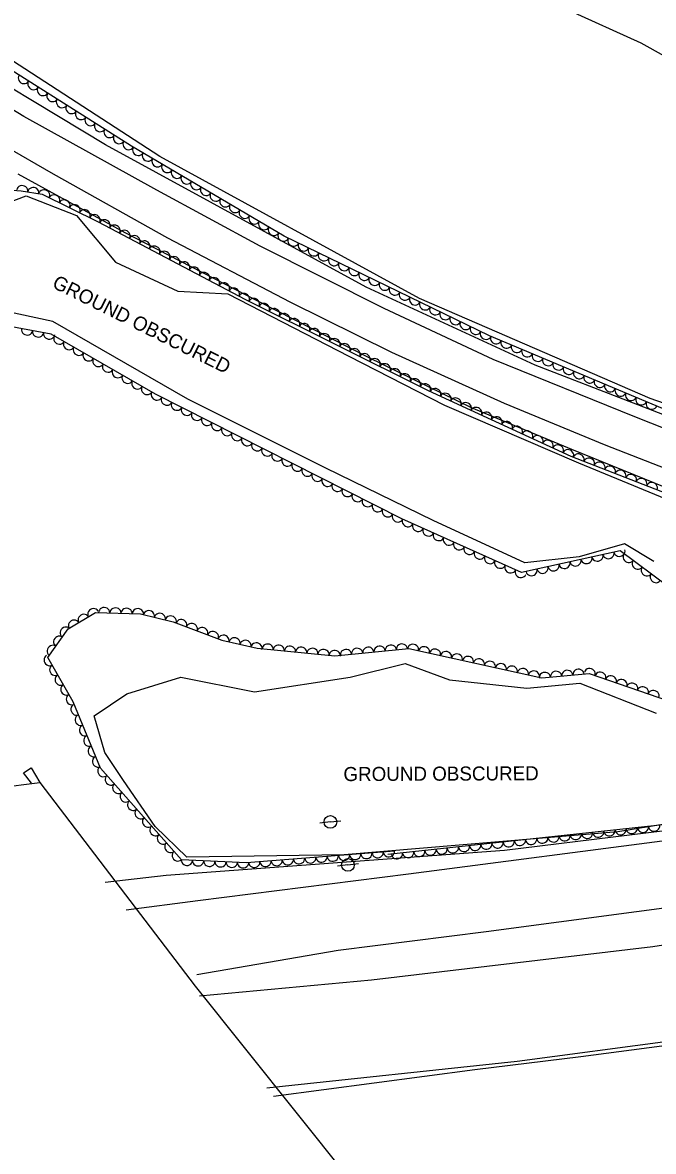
# Model space of a CAD drawing. Extents: x 1746719 to 1766531, y 631721 to 662391.
# Drawn here: x 1764923.1 to 1765147.4, y 632583.4 to 632984.7 of the extents above; entities that cross this region are included whole.
import ezdxf

# ---------------------------------------------------------------- set-up
doc = ezdxf.new("R2010")
doc.units = 0
for name, color, linetype in [('SURVEY - AERIAL SURVEY - Photo Control - Points - Elevations', 7, 'Continuous'), ('SURVEY - AERIAL SURVEY - Photo Control - Points - Locators', 7, 'Continuous'), ('SURVEY - AERIAL SURVEY - Photo Control with Text', 7, 'Continuous'), ('SURVEY - CENTERLINE - Existing Roads - Development', 7, 'Continuous'), ('SURVEY - CENTERLINE - Existing Roads Text', 7, 'Continuous')]:
    doc.layers.add(name, color=color, linetype=linetype)

msp = doc.modelspace()

# ---------------------------------------------------------------- linework, layer by layer
at = {"layer": 'SURVEY - AERIAL SURVEY - Photo Control - Points - Elevations'}
for points in [[(1765405.55, 632796.71), (1765330.18, 632801.39), (1765276.68, 632810.4), (1765227.62, 632820.45), (1765175.33, 632835.88), (1765105.4, 632862.94), (1765045.31, 632890.6), (1764952.52, 632941.27), (1764893.1, 632976.98), (1764852.73, 633007.31), (1764794.71, 633051.44), (1764731.05, 633102.95), (1764684.95, 633147.06), (1764630.12, 633206.72), (1764589.37, 633257.76), (1764542.78, 633315.43), (1764515.94, 633356.98), (1764503.08, 633378.08)], [(1765402.26, 632787.96), (1765361.2, 632790.5), (1765329.28, 632793.31), (1765292.46, 632799.51), (1765251.85, 632808.39), (1765215.1, 632818.14), (1765178.89, 632829.55), (1765140.77, 632844.55), (1765090.46, 632864.92), (1765051.71, 632883.1), (1765007.59, 632905.27), (1764970.77, 632925.15), (1764923.54, 632951.31), (1764880.2, 632977.66)], [(1765391.82, 632775.7), (1765360.92, 632777.57), (1765341.11, 632779.4), (1765324.33, 632781.23), (1765299.09, 632785.14), (1765276.61, 632789.6), (1765253.82, 632794.81), (1765231.23, 632800.66), (1765205.66, 632807.76), (1765181.65, 632815.3), (1765157.05, 632824.01), (1765130.08, 632834.58), (1765094.5, 632849.32), (1765054.39, 632867.46), (1765018.25, 632885.35), (1764974.76, 632908.1), (1764934.05, 632930.78), (1764898.68, 632951.21)], [(1764952.48, 632679.13), (1764974.15, 632681.64), (1765094.48, 632690.51), (1765183.35, 632701.44), (1765281.66, 632726.68), (1765343.44, 632739.05), (1765372.09, 632748.82), (1765371.55, 632753.36), (1765368.65, 632757.53), (1765339.3, 632772.92), (1765297.11, 632779.38), (1765261.51, 632786.73), (1765218.53, 632797.59), (1765190.3, 632804.88), (1765162.76, 632814.94), (1765118.36, 632832.93), (1765082.73, 632847.76), (1765046.16, 632865.6), (1765006.8, 632885.71), (1764959.62, 632910.01), (1764921.46, 632930.83)], [(1764959.86, 632669.29), (1764985.37, 632672.58), (1765060.29, 632682.11), (1765156.9, 632694.65), (1765232.5, 632706.41), (1765288.72, 632716.85), (1765340.55, 632728.51), (1765388.58, 632740.56), (1765439.4, 632754.72)], [(1764985, 632646.34), (1765035.31, 632655.01), (1765087.95, 632661.65), (1765167.23, 632672.1), (1765251.78, 632685.46), (1765339.51, 632703.93), (1765367.1, 632710.21), (1765376.53, 632708.95), (1765377.35, 632708.11), (1765378.23, 632706.75), (1765378.64, 632705.15), (1765377.49, 632703.57), (1765371.62, 632698.98), (1765367.73, 632697.3), (1765362.18, 632696.02), (1765331.43, 632688.57), (1765253.62, 632672.78), (1765147.19, 632656.13), (1765047.13, 632644.27), (1764986, 632638.62)], [(1765344.02, 632569.03), (1765327.17, 632583.68), (1765304.27, 632599.56), (1765285.42, 632609.4), (1765261.41, 632618.77), (1765241.44, 632624.18), (1765220.16, 632626.94), (1765194.12, 632626.8), (1765154.28, 632622.77), (1765098.99, 632615.44), (1765009.92, 632605.91)], [(1765320.19, 632582.94), (1765297.73, 632597.9), (1765272.18, 632610.43), (1765243.85, 632618.9), (1765223.43, 632624.7), (1765190.37, 632624.79), (1765163.91, 632622.68), (1765121.59, 632617.07), (1765083.89, 632612.38), (1765012.26, 632602.97)]]:
    msp.add_lwpolyline(points, dxfattribs=at)
at = {"layer": 'SURVEY - AERIAL SURVEY - Photo Control - Points - Locators'}
for points in [[(1765420.59, 632799.81), (1765352.54, 632801.36), (1765306.68, 632807.82), (1765224.24, 632823.91), (1765146.28, 632851.08), (1765064.26, 632886.58), (1764971.89, 632937.15), (1764891.98, 632988.83), (1764834.38, 633027.43), (1764768.22, 633076.12), (1764713.93, 633122.52), (1764646.51, 633193.22), (1764650.11, 633212.47), (1764635.34, 633243.35), (1764619.24, 633269.36), (1764613.9, 633275.29)], [(1764909.25, 633068.37), (1764938.84, 633053.98), (1764965.49, 633051.38), (1764990.14, 633044.09), (1765000.39, 633032.01), (1765031.93, 633011.83), (1765053.24, 632994.52), (1765083.38, 632993.91), (1765116.7, 632989.36), (1765142.91, 632977.46), (1765166.84, 632964.22), (1765179.57, 632940.86), (1765182.57, 632929.75), (1765206.98, 632913.55), (1765238.34, 632894.81), (1765265.57, 632881.71), (1765294.15, 632875.06), (1765330.01, 632866.88), (1765360.91, 632861.63), (1765392.72, 632858.38)], [(1764916.54, 632920.19), (1764924.4, 632923.1), (1764942.26, 632916.18), (1764956.15, 632899.5), (1764978.28, 632889.26), (1764996.07, 632888.31), (1765039.09, 632866.16), (1765073.09, 632848.69)], [(1765147.54, 632793.13), (1765137.16, 632799.42), (1765121.03, 632794.74), (1765101.74, 632792.61), (1765069.14, 632807.75), (1765030.92, 632826.31), (1764981.81, 632850.84), (1764933.87, 632878.5), (1764905.14, 632884.63)], [(1765073.09, 632848.69), (1765120.74, 632828.22), (1765172.79, 632806.71)], [(1765199.4, 632707.59), (1765134.82, 632697.01), (1765037.41, 632688.82), (1764981.47, 632688.01), (1764970.18, 632698.99), (1764959, 632715.24), (1764952.37, 632725.25), (1764948.57, 632738.24), (1764960.12, 632746.13), (1764979.32, 632751.99), (1765005.59, 632746.85), (1765039.53, 632752.06), (1765059.2, 632756.84), (1765074.9, 632751.06), (1765102.46, 632748.09), (1765121.25, 632749.92), (1765148.44, 632739.25)]]:
    msp.add_lwpolyline(points, dxfattribs=at)
at = {"layer": 'SURVEY - AERIAL SURVEY - Photo Control with Text'}
for points in [[(1765421.97, 632798.07), (1765349.97, 632800.91), (1765276.72, 632812.18), (1765214.84, 632825.79), (1765152.86, 632846.61), (1765089.11, 632873.35), (1765016.1, 632908.74), (1764961.81, 632940.76), (1764903.95, 632977.24), (1764850.97, 633012.42), (1764802.27, 633048.67), (1764748.05, 633090.52), (1764703.67, 633131.64), (1764646.25, 633191), (1764640.08, 633203.27), (1764641.2, 633222.14), (1764617.56, 633262.33), (1764604.44, 633282.31), (1764595.81, 633316.48), (1764603.61, 633330.78)], [(1764793.84, 632968), (1764782.2, 632980.66), (1764777.93, 632995.28), (1764790.08, 633001.97), (1764812.82, 632992.23), (1764867.11, 632954.7), (1764908.11, 632925.96), (1764922.59, 632924.95), (1764930.06, 632923.7), (1764950.01, 632913.91), (1765002.14, 632886.38), (1765067.3, 632853.88), (1765118.03, 632830.56), (1765171.36, 632809.82), (1765229.12, 632790.58), (1765287.61, 632773.65), (1765303.5, 632750.65), (1765303.15, 632741.87), (1765286.32, 632729.03), (1765268.97, 632724.98), (1765183.81, 632703.05), (1765052.93, 632688.94)], [(1765152.84, 632784.11), (1765135.58, 632796.9), (1765100.57, 632789.17), (1765058, 632808.29), (1764970.3, 632852.64), (1764933.26, 632873.94), (1764901.9, 632879.73)], [(1765055.33, 632690.16), (1765002.73, 632686.03), (1764979.58, 632687.05), (1764950.77, 632719.66), (1764941.02, 632743.26), (1764932.05, 632759.05), (1764939.27, 632769.18), (1764949.06, 632774.99), (1764964.97, 632774.49), (1764976.67, 632771.7), (1764993.95, 632765.2), (1765006.54, 632762.28), (1765034.16, 632759.65), (1765060.39, 632762.17), (1765107.72, 632751.76), (1765124.53, 632753.3), (1765166.96, 632738.76)]]:
    msp.add_lwpolyline(points, dxfattribs=at)
for centre, major_axis in [((1764923.51, 632964.91), (-1.69, 1.07)), ((1764926.89, 632962.77), (-1.69, 1.07)), ((1764930.27, 632960.64), (-1.69, 1.07)), ((1764933.66, 632958.51), (-1.69, 1.07)), ((1764937.04, 632956.37), (-1.69, 1.07)), ((1764940.42, 632954.24), (-1.69, 1.07)), ((1764943.81, 632952.11), (-1.69, 1.07)), ((1764947.19, 632949.97), (-1.69, 1.07)), ((1764950.57, 632947.84), (-1.69, 1.07)), ((1764953.96, 632945.71), (-1.69, 1.07)), ((1764957.34, 632943.57), (-1.69, 1.07)), ((1764960.72, 632941.44), (-1.69, 1.07)), ((1764964.15, 632939.37), (-1.72, 1.02)), ((1764967.6, 632937.34), (-1.72, 1.02)), ((1764971.04, 632935.31), (-1.72, 1.02)), ((1764974.49, 632933.28), (-1.72, 1.02)), ((1764977.93, 632931.25), (-1.72, 1.02)), ((1764922.96, 632924.88), (1.97, -0.33)), ((1764981.38, 632929.22), (-1.72, 1.02)), ((1764984.82, 632927.18), (-1.72, 1.02)), ((1764926.91, 632924.23), (1.97, -0.33)), ((1764930.78, 632923.35), (1.8, -0.88)), ((1764934.37, 632921.59), (1.8, -0.88)), ((1764988.27, 632925.15), (-1.72, 1.02)), ((1764991.72, 632923.12), (-1.72, 1.02)), ((1764937.97, 632919.82), (1.8, -0.88)), ((1764941.56, 632918.06), (1.8, -0.88)), ((1764945.15, 632916.3), (1.8, -0.88)), ((1764995.16, 632921.09), (-1.72, 1.02)), ((1764998.61, 632919.06), (-1.72, 1.02)), ((1764948.74, 632914.54), (1.8, -0.88)), ((1764952.29, 632912.71), (1.77, -0.93)), ((1765002.05, 632917.03), (-1.72, 1.02)), ((1765005.5, 632915), (-1.72, 1.02)), ((1764955.83, 632910.84), (1.77, -0.93)), ((1764959.37, 632908.97), (1.77, -0.93)), ((1765008.94, 632912.96), (-1.72, 1.02)), ((1765012.39, 632910.93), (-1.72, 1.02)), ((1764962.91, 632907.1), (1.77, -0.93)), ((1764966.44, 632905.23), (1.77, -0.93)), ((1765015.84, 632908.9), (-1.72, 1.02)), ((1765019.42, 632907.13), (-1.8, 0.87)), ((1764969.98, 632903.37), (1.77, -0.93)), ((1764973.52, 632901.5), (1.77, -0.93)), ((1765023.02, 632905.39), (-1.8, 0.87)), ((1765026.62, 632903.64), (-1.8, 0.87)), ((1765030.22, 632901.9), (-1.8, 0.87)), ((1764977.05, 632899.63), (1.77, -0.93)), ((1764980.59, 632897.76), (1.77, -0.93)), ((1765033.82, 632900.15), (-1.8, 0.87)), ((1765037.42, 632898.41), (-1.8, 0.87)), ((1764984.13, 632895.89), (1.77, -0.93)), ((1764987.66, 632894.02), (1.77, -0.93)), ((1764991.2, 632892.16), (1.77, -0.93)), ((1765041.02, 632896.66), (-1.8, 0.87)), ((1765044.62, 632894.92), (-1.8, 0.87)), ((1764994.74, 632890.29), (1.77, -0.93)), ((1764998.27, 632888.42), (1.77, -0.93)), ((1765048.22, 632893.17), (-1.8, 0.87)), ((1765051.82, 632891.43), (-1.8, 0.87)), ((1765055.42, 632889.68), (-1.8, 0.87)), ((1765001.81, 632886.55), (1.77, -0.93)), ((1765005.39, 632884.76), (1.79, -0.89)), ((1765059.01, 632887.94), (-1.8, 0.87)), ((1765062.61, 632886.19), (-1.8, 0.87)), ((1765008.97, 632882.97), (1.79, -0.89)), ((1765012.55, 632881.19), (1.79, -0.89)), ((1765066.21, 632884.45), (-1.8, 0.87)), ((1765069.81, 632882.7), (-1.8, 0.87)), ((1765016.13, 632879.4), (1.79, -0.89)), ((1765019.7, 632877.62), (1.79, -0.89)), ((1765073.41, 632880.96), (-1.8, 0.87)), ((1765077.01, 632879.21), (-1.8, 0.87)), ((1765080.61, 632877.47), (-1.8, 0.87)), ((1764924.69, 632875.52), (-1.97, 0.36)), ((1764928.62, 632874.8), (-1.97, 0.36)), ((1764932.56, 632874.07), (-1.97, 0.36)), ((1765023.28, 632875.83), (1.79, -0.89)), ((1765026.86, 632874.05), (1.79, -0.89)), ((1765030.44, 632872.26), (1.79, -0.89)), ((1765084.21, 632875.72), (-1.8, 0.87)), ((1765087.81, 632873.98), (-1.8, 0.87)), ((1764936.11, 632872.3), (-1.73, 1)), ((1764939.57, 632870.31), (-1.73, 1)), ((1765034.02, 632870.48), (1.79, -0.89)), ((1765037.6, 632868.69), (1.79, -0.89)), ((1765091.46, 632872.36), (-1.84, 0.77)), ((1765095.15, 632870.81), (-1.84, 0.77)), ((1764943.04, 632868.31), (-1.73, 1)), ((1764946.51, 632866.32), (-1.73, 1)), ((1765041.18, 632866.91), (1.79, -0.89)), ((1765044.76, 632865.12), (1.79, -0.89)), ((1765098.84, 632869.26), (-1.84, 0.77)), ((1765102.53, 632867.72), (-1.84, 0.77)), ((1765106.22, 632866.17), (-1.84, 0.77)), ((1764949.98, 632864.33), (-1.73, 1)), ((1764953.44, 632862.33), (-1.73, 1)), ((1765048.34, 632863.34), (1.79, -0.89)), ((1765051.92, 632861.55), (1.79, -0.89)), ((1765109.91, 632864.62), (-1.84, 0.77)), ((1765113.6, 632863.08), (-1.84, 0.77)), ((1765117.29, 632861.53), (-1.84, 0.77)), ((1764956.91, 632860.34), (-1.73, 1)), ((1764960.38, 632858.34), (-1.73, 1)), ((1765055.5, 632859.77), (1.79, -0.89)), ((1765059.08, 632857.98), (1.79, -0.89)), ((1765062.66, 632856.2), (1.79, -0.89)), ((1765120.97, 632859.98), (-1.84, 0.77)), ((1765124.66, 632858.44), (-1.84, 0.77)), ((1764963.85, 632856.35), (-1.73, 1)), ((1764967.31, 632854.36), (-1.73, 1)), ((1765066.24, 632854.41), (1.79, -0.89)), ((1765069.86, 632852.71), (1.82, -0.84)), ((1765128.35, 632856.89), (-1.84, 0.77)), ((1765132.04, 632855.34), (-1.84, 0.77)), ((1765135.73, 632853.79), (-1.84, 0.77)), ((1764970.8, 632852.39), (-1.78, 0.9)), ((1764974.36, 632850.58), (-1.78, 0.9)), ((1765073.49, 632851.04), (1.82, -0.84)), ((1765077.13, 632849.37), (1.82, -0.84)), ((1765139.42, 632852.25), (-1.84, 0.77)), ((1765143.11, 632850.7), (-1.84, 0.77)), ((1764977.93, 632848.78), (-1.78, 0.9)), ((1764981.5, 632846.97), (-1.78, 0.9)), ((1765080.76, 632847.7), (1.82, -0.84)), ((1765084.4, 632846.03), (1.82, -0.84)), ((1765088.03, 632844.35), (1.82, -0.84)), ((1765146.8, 632849.15), (-1.84, 0.77)), ((1764985.07, 632845.17), (-1.78, 0.9)), ((1764988.64, 632843.36), (-1.78, 0.9)), ((1764992.21, 632841.56), (-1.78, 0.9)), ((1765091.66, 632842.68), (1.82, -0.84)), ((1765095.3, 632841.01), (1.82, -0.84)), ((1764995.78, 632839.75), (-1.78, 0.9)), ((1764999.35, 632837.95), (-1.78, 0.9)), ((1765098.93, 632839.34), (1.82, -0.84)), ((1765102.57, 632837.67), (1.82, -0.84)), ((1765106.2, 632836), (1.82, -0.84)), ((1765002.92, 632836.14), (-1.78, 0.9)), ((1765006.49, 632834.34), (-1.78, 0.9)), ((1765109.84, 632834.33), (1.82, -0.84)), ((1765113.47, 632832.66), (1.82, -0.84)), ((1765010.06, 632832.53), (-1.78, 0.9)), ((1765013.63, 632830.73), (-1.78, 0.9)), ((1765117.1, 632830.99), (1.82, -0.84)), ((1765120.81, 632829.48), (1.86, -0.73)), ((1765124.54, 632828.03), (1.86, -0.73)), ((1765017.2, 632828.92), (-1.78, 0.9)), ((1765020.77, 632827.12), (-1.78, 0.9)), ((1765024.34, 632825.31), (-1.78, 0.9)), ((1765128.26, 632826.58), (1.86, -0.73)), ((1765131.99, 632825.13), (1.86, -0.73)), ((1765027.91, 632823.51), (-1.78, 0.9)), ((1765031.48, 632821.7), (-1.78, 0.9)), ((1765135.72, 632823.68), (1.86, -0.73)), ((1765139.45, 632822.23), (1.86, -0.73)), ((1765143.18, 632820.78), (1.86, -0.73)), ((1765035.05, 632819.9), (-1.78, 0.9)), ((1765038.62, 632818.09), (-1.78, 0.9)), ((1765146.9, 632819.33), (1.86, -0.73)), ((1765042.19, 632816.29), (-1.78, 0.9)), ((1765045.76, 632814.48), (-1.78, 0.9)), ((1765049.33, 632812.68), (-1.78, 0.9)), ((1765052.9, 632810.87), (-1.78, 0.9)), ((1765056.47, 632809.07), (-1.78, 0.9)), ((1765060.08, 632807.36), (-1.82, 0.82)), ((1765063.73, 632805.72), (-1.82, 0.82)), ((1765067.38, 632804.08), (-1.82, 0.82)), ((1765071.03, 632802.44), (-1.82, 0.82)), ((1765074.67, 632800.8), (-1.82, 0.82)), ((1765078.32, 632799.16), (-1.82, 0.82)), ((1765081.97, 632797.52), (-1.82, 0.82)), ((1765085.62, 632795.88), (-1.82, 0.82)), ((1765089.27, 632794.24), (-1.82, 0.82)), ((1765123.62, 632794.26), (-1.95, -0.43)), ((1765127.53, 632795.12), (-1.95, -0.43)), ((1765131.44, 632795.99), (-1.95, -0.43)), ((1765135.34, 632796.85), (-1.95, -0.43)), ((1765138.6, 632794.67), (-1.61, 1.19)), ((1765092.92, 632792.6), (-1.82, 0.82)), ((1765096.57, 632790.96), (-1.82, 0.82)), ((1765100.22, 632789.33), (-1.82, 0.82)), ((1765104.1, 632789.94), (-1.95, -0.43)), ((1765108, 632790.81), (-1.95, -0.43)), ((1765111.91, 632791.67), (-1.95, -0.43)), ((1765115.81, 632792.53), (-1.95, -0.43)), ((1765119.72, 632793.4), (-1.95, -0.43)), ((1765141.81, 632792.29), (-1.61, 1.19)), ((1765145.03, 632789.9), (-1.61, 1.19)), ((1765148.24, 632787.52), (-1.61, 1.19)), ((1764944.79, 632772.46), (1.72, 1.02)), ((1764948.23, 632774.5), (1.72, 1.02)), ((1764952.09, 632774.9), (2, -0.06)), ((1764956.09, 632774.77), (2, -0.06)), ((1764960.08, 632774.65), (2, -0.06)), ((1764964.08, 632774.52), (2, -0.06)), ((1764968, 632773.77), (1.95, -0.46)), ((1764971.89, 632772.84), (1.95, -0.46)), ((1764975.78, 632771.91), (1.95, -0.46)), ((1764938.35, 632767.89), (1.16, 1.63)), ((1764941.35, 632770.41), (1.72, 1.02)), ((1764979.56, 632770.61), (1.87, -0.7)), ((1764983.3, 632769.21), (1.87, -0.7)), ((1764987.04, 632767.8), (1.87, -0.7)), ((1764936.03, 632764.63), (1.16, 1.63)), ((1764990.79, 632766.39), (1.87, -0.7)), ((1764994.55, 632765.06), (1.95, -0.45)), ((1764998.45, 632764.16), (1.95, -0.45)), ((1764933.71, 632761.38), (1.16, 1.63)), ((1765002.35, 632763.25), (1.95, -0.45)), ((1765006.24, 632762.35), (1.95, -0.45)), ((1765010.22, 632761.93), (1.99, -0.19)), ((1765014.2, 632761.55), (1.99, -0.19)), ((1765018.18, 632761.17), (1.99, -0.19)), ((1765022.17, 632760.79), (1.99, -0.19)), ((1765026.15, 632760.41), (1.99, -0.19)), ((1765030.13, 632760.03), (1.99, -0.19)), ((1765038.09, 632760.03), (1.99, 0.19)), ((1765042.08, 632760.41), (1.99, 0.19)), ((1765046.06, 632760.79), (1.99, 0.19)), ((1765050.04, 632761.18), (1.99, 0.19)), ((1765054.02, 632761.56), (1.99, 0.19)), ((1765058, 632761.94), (1.99, 0.19)), ((1765061.95, 632761.83), (1.95, -0.43)), ((1765065.86, 632760.97), (1.95, -0.43)), ((1765069.77, 632760.11), (1.95, -0.43)), ((1764932.61, 632758.06), (-0.99, 1.74)), ((1765034.11, 632759.65), (1.99, -0.19)), ((1765073.67, 632759.25), (1.95, -0.43)), ((1765077.58, 632758.39), (1.95, -0.43)), ((1765081.49, 632757.53), (1.95, -0.43)), ((1765085.39, 632756.67), (1.95, -0.43)), ((1764934.59, 632754.58), (-0.99, 1.74)), ((1765089.3, 632755.81), (1.95, -0.43)), ((1765093.21, 632754.95), (1.95, -0.43)), ((1765097.11, 632754.09), (1.95, -0.43)), ((1765101.02, 632753.23), (1.95, -0.43)), ((1765104.92, 632752.37), (1.95, -0.43)), ((1765112.84, 632752.23), (1.99, 0.18)), ((1765116.82, 632752.59), (1.99, 0.18)), ((1765120.8, 632752.96), (1.99, 0.18)), ((1765124.77, 632753.22), (1.89, -0.65)), ((1765128.56, 632751.92), (1.89, -0.65)), ((1764936.56, 632751.1), (-0.99, 1.74)), ((1765108.85, 632751.86), (1.99, 0.18)), ((1765132.34, 632750.62), (1.89, -0.65)), ((1765136.12, 632749.32), (1.89, -0.65)), ((1765139.91, 632748.03), (1.89, -0.65)), ((1764938.54, 632747.62), (-0.99, 1.74)), ((1764940.51, 632744.14), (-0.99, 1.74)), ((1765143.69, 632746.73), (1.89, -0.65)), ((1765147.48, 632745.43), (1.89, -0.65)), ((1764942.16, 632740.5), (-0.76, 1.85)), ((1764943.68, 632736.8), (-0.76, 1.85)), ((1764945.21, 632733.11), (-0.76, 1.85)), ((1764946.74, 632729.41), (-0.76, 1.85)), ((1764948.27, 632725.71), (-0.76, 1.85)), ((1764949.79, 632722.02), (-0.76, 1.85)), ((1764951.73, 632718.57), (-1.32, 1.5)), ((1764954.38, 632715.58), (-1.32, 1.5)), ((1764957.02, 632712.58), (-1.32, 1.5)), ((1764959.67, 632709.58), (-1.32, 1.5)), ((1764962.32, 632706.58), (-1.32, 1.5)), ((1764964.97, 632703.58), (-1.32, 1.5)), ((1764967.62, 632700.59), (-1.32, 1.5)), ((1764970.27, 632697.59), (-1.32, 1.5)), ((1765135.76, 632697.87), (-1.99, -0.21)), ((1765139.74, 632698.29), (-1.99, -0.21)), ((1765143.71, 632698.72), (-1.99, -0.21)), ((1765147.69, 632699.15), (-1.99, -0.21)), ((1764972.91, 632694.59), (-1.32, 1.5)), ((1765095.99, 632693.58), (-1.99, -0.21)), ((1765099.97, 632694.01), (-1.99, -0.21)), ((1765103.94, 632694.43), (-1.99, -0.21)), ((1765107.92, 632694.86), (-1.99, -0.21)), ((1765111.9, 632695.29), (-1.99, -0.21)), ((1765115.88, 632695.72), (-1.99, -0.21)), ((1765119.85, 632696.15), (-1.99, -0.21)), ((1765123.83, 632696.58), (-1.99, -0.21)), ((1765127.81, 632697.01), (-1.99, -0.21)), ((1765131.78, 632697.44), (-1.99, -0.21)), ((1764975.56, 632691.59), (-1.32, 1.5)), ((1764978.21, 632688.6), (-1.32, 1.5)), ((1765049.35, 632689.69), (-1.99, -0.16)), ((1765053.33, 632690), (-1.99, -0.16)), ((1765060.2, 632689.72), (-1.99, -0.21)), ((1765064.18, 632690.15), (-1.99, -0.21)), ((1765068.15, 632690.58), (-1.99, -0.21)), ((1765072.13, 632691), (-1.99, -0.21)), ((1765076.11, 632691.43), (-1.99, -0.21)), ((1765080.08, 632691.86), (-1.99, -0.21)), ((1765084.06, 632692.29), (-1.99, -0.21)), ((1765088.04, 632692.72), (-1.99, -0.21)), ((1765092.01, 632693.15), (-1.99, -0.21)), ((1764981.51, 632686.96), (-2, 0.09)), ((1764985.51, 632686.79), (-2, 0.09)), ((1764989.5, 632686.61), (-2, 0.09)), ((1764993.5, 632686.43), (-2, 0.09)), ((1764997.49, 632686.26), (-2, 0.09)), ((1765001.49, 632686.08), (-2, 0.09)), ((1765005.48, 632686.24), (-1.99, -0.16)), ((1765009.47, 632686.56), (-1.99, -0.16)), ((1765013.46, 632686.87), (-1.99, -0.16)), ((1765017.44, 632687.18), (-1.99, -0.16)), ((1765021.43, 632687.5), (-1.99, -0.16)), ((1765025.42, 632687.81), (-1.99, -0.16)), ((1765029.41, 632688.12), (-1.99, -0.16)), ((1765033.39, 632688.44), (-1.99, -0.16)), ((1765037.38, 632688.75), (-1.99, -0.16)), ((1765041.37, 632689.06), (-1.99, -0.16)), ((1765045.36, 632689.38), (-1.99, -0.16)), ((1765056.22, 632689.29), (-1.99, -0.21))]:
    msp.add_ellipse(centre, major_axis=major_axis, ratio=0.940188, start_param=0, end_param=3.141593, dxfattribs=at)
at = {"layer": 'SURVEY - CENTERLINE - Existing Roads - Development'}
for p, q in [((1765032.57, 632700.57), (1765028.85, 632700.15)), ((1765032.57, 632700.57), (1765036.3, 632700.98)), ((1765038.78, 632685.28), (1765042.51, 632685.73)), ((1765038.78, 632685.28), (1765035.06, 632684.84))]:
    msp.add_line(p, q, dxfattribs=at)
for centre in [(1765032.57, 632700.57), (1765038.78, 632685.28)]:
    msp.add_circle(centre, 2.25, dxfattribs=at)
at = {"layer": 'SURVEY - CENTERLINE - Existing Roads Text'}
for p, q in [((1764923.42, 632717.96), (1764926.14, 632719.81)), ((1764926.2, 632714.38), (1764923.42, 632717.96)), ((1764926.14, 632719.81), (1764929.23, 632714.53)), ((1764749.37, 632692.41), (1764929.23, 632714.53)), ((1764929.23, 632714.53), (1764984.51, 632642.19)), ((1764984.51, 632642.19), (1765045.82, 632565.48))]:
    msp.add_line(p, q, dxfattribs=at)

# ---------------------------------------------------------------- texts
at = {"layer": 'SURVEY - AERIAL SURVEY - Photo Control - Points - Locators'}
for rotation, p in [(333.4958, (1764933.27, 632890.7)), (0.2494, (1765037.19, 632715.07))]:
    msp.add_text('GROUND OBSCURED', height=5, rotation=rotation, dxfattribs=at).set_placement(p)

doc.saveas('drawing.dxf')
